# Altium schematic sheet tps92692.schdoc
size 426 x 301 mm; SheetNumber: 2; SheetTotal: 8
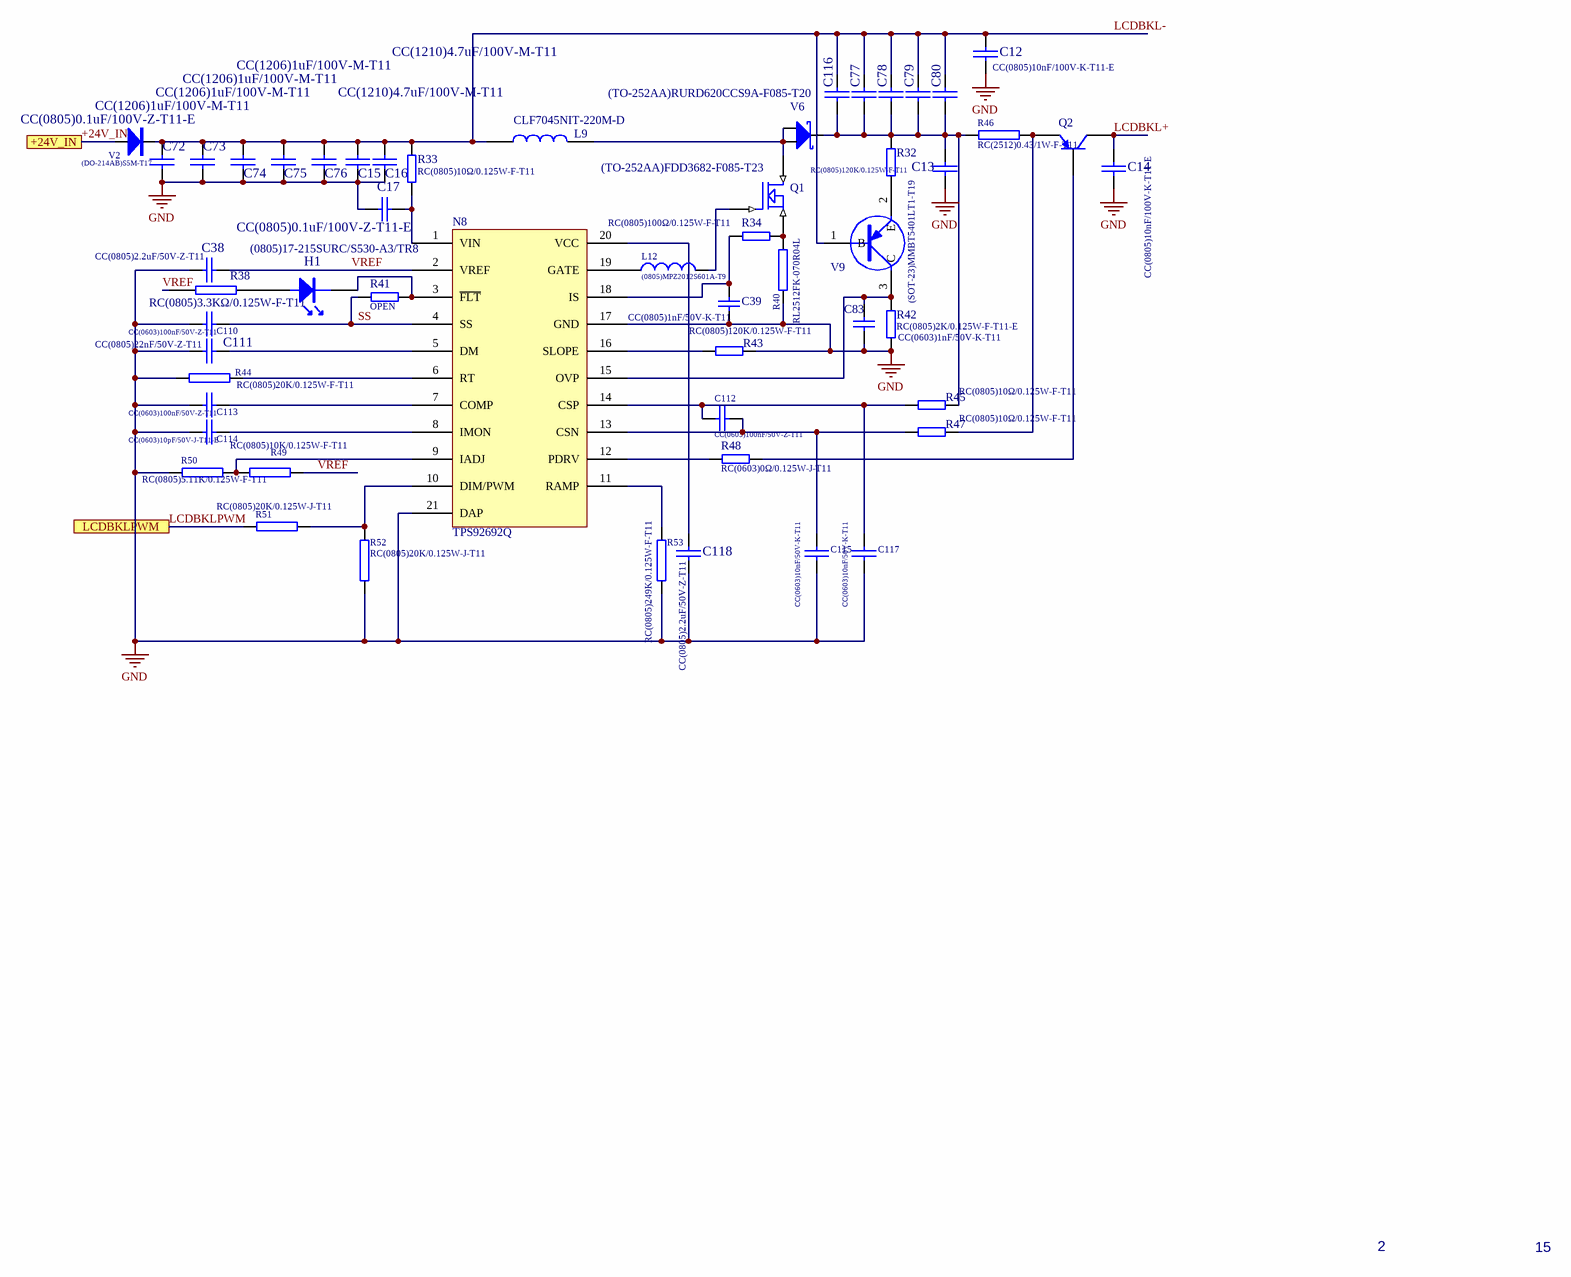
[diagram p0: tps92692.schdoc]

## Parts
C12  CC(0805)10nF/100V-K-T11-E  [0805]
C13  CC(1206)1uF/100V-M-T11  [1206]  (value not drawn)
C14  CC(0805)10nF/100V-K-T11-E  [0805]
C15  CC(1210)4.7uF/100V-M-T11  [1210]
C16  CC(1210)4.7uF/100V-M-T11  [1210]
C17  CC(0805)0.1uF/100V-Z-T11-E  [0805]
C38  CC(0805)2.2uF/50V-Z-T11  [0805]
C39  CC(0805)1nF/50V-K-T11  [0805]
C72  CC(0805)0.1uF/100V-Z-T11-E  [0805]
C73  CC(1206)1uF/100V-M-T11  [1206]
C74  CC(1206)1uF/100V-M-T11  [1206]
C75  CC(1206)1uF/100V-M-T11  [1206]
C76  CC(1206)1uF/100V-M-T11  [1206]
C77  CC(1206)1uF/100V-M-T11  [1206]  (value not drawn)
C78  CC(1206)1uF/100V-M-T11  [1206]  (value not drawn)
C79  CC(1206)1uF/100V-M-T11  [1206]  (value not drawn)
C80  CC(1206)1uF/100V-M-T11  [1206]  (value not drawn)
C83  CC(0603)1nF/50V-K-T11  [0603]
C110  CC(0603)100nF/50V-Z-T11  [0603]
C111  CC(0805)22nF/50V-Z-T11  [0805]
C112  CC(0603)100nF/50V-Z-T11  [0603]
C113  CC(0603)100nF/50V-Z-T11  [0603]
C114  CC(0603)10pF/50V-J-T11-E  [0603]
C115  CC(0603)10nF/50V-K-T11  [0603]
C116  CC(0805)0.1uF/100V-Z-T11-E  [0805]  (value not drawn)
C117  CC(0603)10nF/50V-K-T11  [0603]
C118  CC(0805)2.2uF/50V-Z-T11  [0805]
H1  (0805)17-215SURC/S530-A3/TR8  [0805LED]
L9  CLF7045NIT-220M-D  [CLF7045]
L12  (0805)MPZ2012S601A-T9  [0805]
N8  TPS92692Q  [PWR(R-PDSO-G20)]
Q1  (TO-252AA)FDD3682-F085-T23  [DPAK]
Q2  (TO-252)STDP6F6  [DPAK]  (value not drawn)
R32  RC(0805)120K/0.125W-F-T11  [0805]
R33  RC(0805)10Ω/0.125W-F-T11  [0805]
R34  RC(0805)100Ω/0.125W-F-T11  [0805]
R38  RC(0805)3.3KΩ/0.125W-F-T11  [0805]
R40  RL2512FK-070R04L  [2512]
R41  OPEN  [0603]
R42  RC(0805)2K/0.125W-F-T11-E  [0805]
R43  RC(0805)120K/0.125W-F-T11  [0805]
R44  RC(0805)20K/0.125W-F-T11  [0805]
R45  RC(0805)10Ω/0.125W-F-T11  [0805]
R46  RC(2512)0.43/1W-F-T11  [2512]
R47  RC(0805)10Ω/0.125W-F-T11  [0805]
R48  RC(0603)0Ω/0.125W-J-T11  [0603]
R49  RC(0805)10K/0.125W-F-T11  [0805]
R50  RC(0805)5.11K/0.125W-F-T11  [0805]
R51  RC(0805)20K/0.125W-J-T11  [0805]
R52  RC(0805)20K/0.125W-J-T11  [0805]
R53  RC(0805)249K/0.125W-F-T11  [0805]
V2  (DO-214AB)S5M-T17  [SMC]
V6  (TO-252AA)RURD620CCS9A-F085-T20  [DPAK]
V9  (SOT-23)MMBT5401LT1-T19  [SOT-23]

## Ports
+24V_IN, LCDBKLPWM

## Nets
GND: C12.2 C13.1 C14.2 C15.2 C16.2 C17.1 C38.2 C39.1 C72.2 C73.2 C74.2 C75.2 C76.2 C83.1 C110.1 C111.2 C113.1 C114.1 C115.2 C117.2 C118.2 N8.17(GND) N8.21(DAP) R40.1 R42.2 R43.2 R44.1 R50.2 R52.2 R53.2
+24V_IN: V2.1(A) ; port +24V_IN
LCDBKL+: C14.1 Q2.2(C)
LCDBKL-: C12.1 C15.1 C16.1 C72.1 C73.1 C74.1 C75.1 C76.1 C77.1 C78.1 C79.1 C80.1 C116.1 L9.1 R33.2 V2.2(K) V9.1(B)
LCDBKLPWM: R51.2 ; port LCDBKLPWM
SS: C110.2 N8.4(SS) R41.1
VREF: C38.1 N8.2(VREF) R38.1 R49.1
NetC13_2: C13.2 C77.2 C78.2 C79.2 C80.2 C116.2 R32.2 R45.2 R46.2 V6.2(K)
NetC17_2: C17.2 N8.1(VIN) R33.1
NetC39_2: C39.2 N8.18(IS) R34.1
NetC83_2: C83.2 N8.15(OVP) R42.1 V9.3(C)
NetC111_1: C111.1 N8.5(DM)
NetC112_1: C112.1 C115.1 N8.13(CSN) R47.1
NetC112_2: C112.2 C117.1 N8.14(CSP) R45.1
NetC113_2: C113.2 N8.7(COMP)
NetC114_2: C114.2 N8.8(IMON)
NetC118_1: C118.1 N8.20(VCC)
NetH1_1: H1.1 R38.2
NetH1_2: H1.2 N8.3(~{FLT}) R41.2
NetL9_2: L9.2 Q1.2(D) V6.1(A) V6.3(A)
NetL12_1: L12.1 N8.19(GATE)
NetL12_2: L12.2 Q1.1(G)
NetN8_6: N8.6(RT) R44.2
NetN8_9: N8.9(IADJ) R49.2 R50.1
NetN8_10: N8.10(DIM/PWM) R51.1 R52.1
NetN8_11: N8.11(RAMP) R53.1
NetN8_12: N8.12(PDRV) R48.1
NetN8_16: N8.16(SLOPE) R43.1
NetQ1_3: Q1.3(S) R34.2 R40.2
NetQ2_1: Q2.1(B) R48.2
NetQ2_3: Q2.3(E) R46.1 R47.2
NetR32_1: R32.1 V9.2(E)

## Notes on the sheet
- 2
- 15

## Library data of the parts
C12-C17 C38 C72-C80 C110-C118 = CAP: Capacitor
C39 C83 = Cap: Capacitor
H1 = LED
L9 = INDUCTOR
L12 = 贴片磁珠 (0805)MPZ2012S601A-T9
Q1 = MOSFET N
Q2 = MJD32C
R32-R34 R41-R43 R45 R47 R48 = 贴片电阻 RC(0603)10K/0.0625W-J-T11
R38 R40 R44 R46 R49-R53 = RES2
V2 = 1N4007: Diode
V6 = SX36: Schottky Diode
V9 = MJD32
